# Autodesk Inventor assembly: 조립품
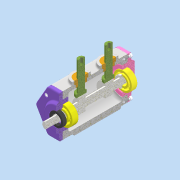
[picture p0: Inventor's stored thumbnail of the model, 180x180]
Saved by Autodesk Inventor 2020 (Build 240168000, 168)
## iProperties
Created: 2021-06
Part Number: 조립품
Document SubType Name: Assembly
Designer: MIRAE
Author: MIRAE
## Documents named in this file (11)
- D:\710606V1035\조립품.iam
- D:\710606V1035\본체.ipt
- D:\710606V1035\뒷커버.ipt
- D:\710606V1035\베어링 6203.ipt
- D:\710606V1035\베어링 6302.ipt
- D:\710606V1035\볼트 M4.ipt
- D:\710606V1035\부시.ipt
- D:\710606V1035\슬라이더.ipt
- D:\710606V1035\앞커버.ipt
- D:\710606V1035\오일실.ipt
- D:\710606V1035\편심축.ipt
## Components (10 placed, 3 different names)
1. 7-베어링 6203:1
2. 8-오일실:1
3. 9-M4-소켓머리:1 — 각도:2
4. 9-M4-소켓머리:3
5. 9-M4-소켓머리:4
6. 9-M4-소켓머리:5
7. 9-M4-소켓머리:2 — 각도:1
8. 9-M4-소켓머리:6
9. 9-M4-소켓머리:7
10. 9-M4-소켓머리:8
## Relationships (2: Angle 2)
- 각도:1 [Angle]: 9-M4-소켓머리:2
- 각도:2 [Angle]: 9-M4-소켓머리:1
